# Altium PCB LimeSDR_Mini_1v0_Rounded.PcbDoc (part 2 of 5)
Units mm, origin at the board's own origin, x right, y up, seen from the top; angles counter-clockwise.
Board outline 69.3 x 52.3 mm, 8 copper layers (Top, L2, L3, L4, L5, L6, L7, Bottom), stack 1.555 mm thick; 371 components, 281 nets, 1644 pads, 778 vias.
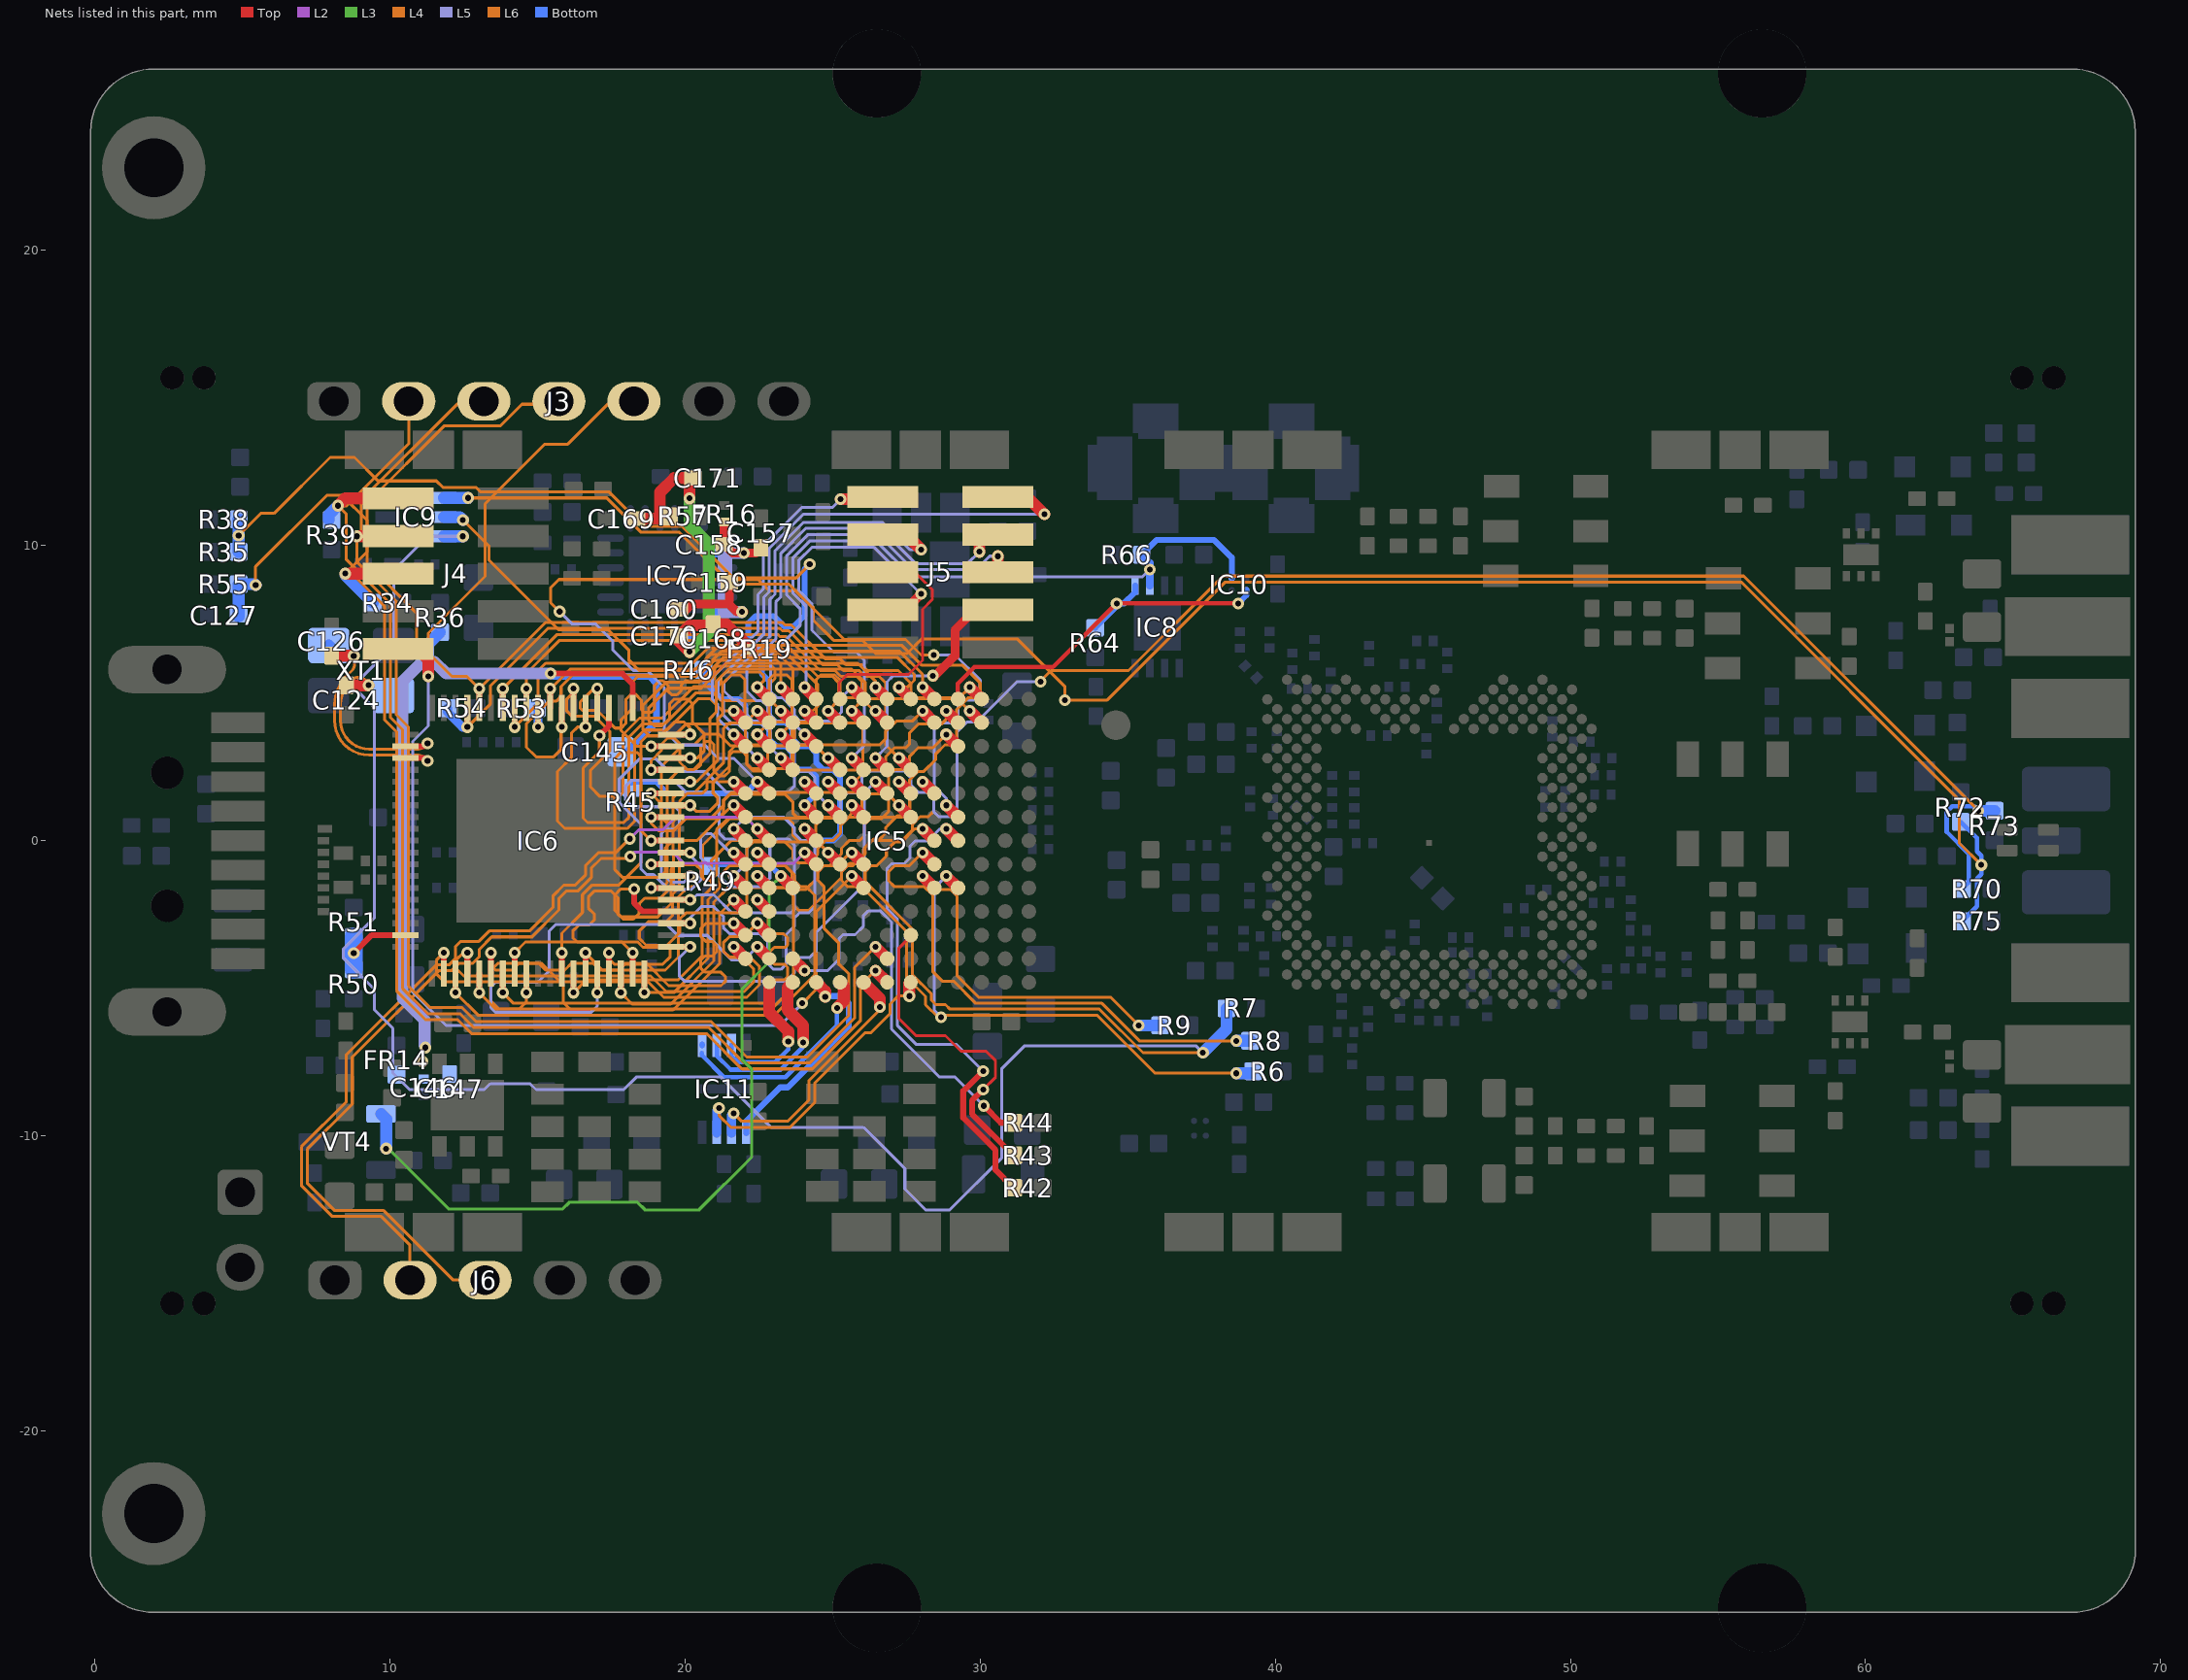
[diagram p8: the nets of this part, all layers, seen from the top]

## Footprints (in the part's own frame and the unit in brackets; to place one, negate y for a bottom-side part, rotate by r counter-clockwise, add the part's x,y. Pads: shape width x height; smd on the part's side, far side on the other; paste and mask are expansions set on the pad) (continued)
RES0805#1 [mm] "Chip Resistor, Body 2.0x1.2mm, 0805, IPC Medium Density"
  round 0.254 on Mech14: 0(0,0)
  rrect25% 0.8x1.3 smd: 1(-1,0) 2(1,0)
  Top pour cut-out: -0.6,0.75 0.6,0.75 0.6,-0.75 -0.6,-0.75
  silkscreen extent -0.38,-0.64 0.38,0.64, body extent -1.1,-0.67 1.1,0.68, height 0.69
RES0805#2 [mm] "Chip Resistor, Body 2.0x1.2mm, 0805, IPC Medium Density"
  round 0.254 on Mech15: 0(0,0)
  rrect25% 0.8x1.3 smd: 1(-1,0) 2(1,0)
  Top pour cut-out: -0.6,0.75 0.6,0.75 0.6,-0.75 -0.6,-0.75
  silkscreen extent -0.38,-0.63 0.38,0.64, body extent -1.1,-0.67 1.1,0.68, height 0.69
RES0805_0603 [mm] "Universal 0805 0603 footprint"
  round 0.254 on Mech15: 0(0,0)
  rrect25% 1x1.3 smd paste-3: 1(-0.9,0) 2(0.9,0)
  Top pour cut-out: -0.4,0.725 0.4,0.725 0.4,-0.775 -0.4,-0.775
  silkscreen extent -0.23,-0.7 0.23,0.7, body extent -1.1,-0.67 1.1,0.68, height 0.69
RFI_SHIELD_CLPS_MINI [mm] "RFI SHIELD CLIP MINI TIN SMD, S0971-46R"
  rect 2x1.3 smd mask+0.05: 1(-2,0) 1(2,0)
  rect 1.4x1.3 smd mask+0.05: 1(0,0)
  body extent -2.9,-0.5 2.9,0.5, height 1
SKY13411-374LF [mm]
  rect 0.35x0.25 smd mask+0.05: 1(-0.725,0.5) 2(-0.725,0) 3(-0.725,-0.5) 4(0.725,-0.5) 5(0.725,0) 6(0.725,0.5)
  rect 0.7x1.2 smd mask+0.05: PAD(0,0)
  silkscreen extent -1.14,-0.8 0.7,0.86, body extent -0.75,-0.75 0.75,0.75, height 0.48
SMA_CONNECTOR_BOARD_EDGE_SM [mm]
  rect 2x4.25 smd: 1(0,0)
  rect 2x4 smd far side: 2(-2.77,-0.1) 2(2.77,-0.1)
  rect 2x4 smd: 2(-2.77,-0.1) 2(2.77,-0.1)
  silkscreen extent -4.3,-1.9 4.3,2.5, body extent -3,-11.8 3,1.8, height 3.4
SOT23-3 [mm] "SOT23, 3 pin"
  round 0.5 on Mech14: 0(0,0)
  rrect25% 1x0.6 smd: D(1.15,0) G(-1.15,0.95) S(-1.15,-0.95)
  silkscreen extent -1.25,-1.45 0.38,1.81, body extent -1.4,-1.45 1.4,1.45, height 1.29
SWD_10_pin [mm]
  rect 0.75x2.4 smd: 1(-2.55,-1.95) 2(-2.55,1.95) 3(-1.275,-1.95) 4(-1.275,1.95) 5(0,-1.95) 6(0,1.95) 7(1.275,-1.95) 8(1.275,1.95) 9(2.55,-1.95) 10(2.55,1.95)
  silkscreen extent -3.2,-3.4 3.2,3.4, body extent -3.17,-2.75 3.17,2.75, height 6.37
USB3A_SM [mm]
  rect 0.7x1.8 smd: 1(-3,-1.2) 2(-1,-1.2) 3(1,-1.2) 4(3,-1.2) 5(4,-1.2) 6(2,-1.2) 7(0,-1.2) 8(-2,-1.2) 9(-4,-1.2)
  oval 1.6x4 hole 1 slot 2.5 at 90 deg: 10(-5.8,1.2) 10(5.8,1.2)
  round 1.1 hole 1.1 unplated: 11(-2.2,1.2) 11(2.3,1.2)
  silkscreen extent -6.95,-2.55 7.05,3.6, body extent -6,-1.75 6,19, height 1.8
W25Q40EWUXIE_8-USON [mm]
  rect 0.8x0.3 smd mask+0.05: 1(-1.475,0.75) 2(-1.475,0.25) 3(-1.475,-0.25) 4(-1.475,-0.75) 5(1.475,-0.75) 6(1.475,-0.25) 7(1.475,0.25) 8(1.475,0.75)
  rect 0.3x1.8 smd mask+0.05: PAD(0,0)
  silkscreen extent -1.55,-1.1 1,1.27, body extent -1.51,-1 1.51,1, height 0.6
WURTHELECTRONIC_RF_SHIELD [mm] "Man. part nr.: 36003250"
  body extent 0,0 26.8,26.8, height 3.1

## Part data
C1 C2 C3 C4 C5 C6 C7 C8 C9 C10 C11 C12 C13 C14 C15 C16 C17 C18 C19 C20 C21 C22 C23 C24 C25 C26 C27 C28 C29 C30 C31 C32 C33 C34 C35 C36 C37 C38 C39 C40 C41 C42 C43 C44 C45 C46 C47 C48 C49 C50 C51 C52 C53 C54 C55 C56 C57 C58 C59 C60 C61 C62 C63 C64 C65 C66 C67 C68 C69 C70 C71 C72 C73 C74 C75 C76 C77 C78 C79 C80 C81 C82 C83 C84 C85 C86 C87 C89 C90 C91 C92 C93 C94 C96 C97 C98 C99 C100 C101 C103 C104 C105 C106 C107 C109 C110 C111 C113 C114 C115 C116 C117 C118 C119 C120 C121 C122 C124 C126 C129 C130 C131 C132 C133 C134 C135 C136 C138 C139 C140 C141 C142 C143 C144 C146 C147 C148 C149 C151 C152 C153 C154 C155 C156 C157 C158 C159 C160 C161 C164 C165 C166 C167 C168 C169 C170 C171 C173 C178 C179 C183 MN3 MN4 MN5 MN6 MN11 MN12 MN13 MN14 MN15 MN16 MN17 MN18 MN19 MN21 MN22: library part Cap_0402
C88 C95 C102 C108 C112 C123 C125 C127 C128 C137 C145 C150 C162 C163 C172 C174 C175 C176 C177 C180 C181 C182 C184: library part Cap_0603
FR1 FR2 FR3 FR4 FR5 FR6 FR7 FR8 FR9 FR10 FR11 FR12 FR13 FR14 FR15 FR16 FR17 FR18 FR19 FR20 FR21 FR22: library part Ferrite
IC1: library part LMS7002Mr3, "Schematic symbol revision 3. Default footprint - 0.31mm pad"
IC9: library part AD5601BKSZ-REEL7, "Single 8-Bit nanoDAC with SPI Interface in LFCSP and SC70, 2.7 to 5.5 V, <100 uA, -40 to +125 degC, KS-6, Pb-Free, Reel"
IC12 IC13: "LXDC55KAAA-205"
J1 J2: library part RF_IF_connector, "CONN SMA JACK STR 50OHM EDGE MNT"
J3: library part Header7P, "Header, 7-pin"
J4 J5: library part "Header 5X2_SWD", "Header, 5-Pin, Dual row"
J6: library part Header5P, "Header, 5-pin"
J8 J9: library part RF_IF_connector, "CONN UMC RCPT STR 50 OHM SMD"
J10: library part Jumper
LED1: library part LED_green_red_SMD
LED2: library part LED_green_red_right_angle, "160-2033-1-ND"
MECH1 MECH2 MECH3 MECH4 MECH6 MECH8 MECH9 MECH10 MECH11 MECH12 MECH13 MECH14: library part RFI_SHIELD_CLIP
MECH5 MECH7 MECH15: library part RFI_SHIELD_1
MN1 MN2 MN7 MN8 MN20 MN23 MN24: library part Inductor_0603
MN9 MN10 R1 R2 R3 R4 R5 R6 R7 R8 R9 R10 R11 R12 R13 R14 R15 R16 R17 R18 R19 R20 R21 R22 R23 R24 R25 R26 R27 R28 R29 R30 R31 R32 R33 R34 R35 R36 R37 R38 R39 R40 R41 R42 R43 R44 R45 R46 R47 R48 R49 R50 R51 R52 R53 R54 R55 R56 R57 R58 R59 R60 R61 R62 R63 R64 R65 R66 R67 R68 R69 R70 R71 R72 R73 R74 R75 R76 R77 R78 R79 R80 R81 R82 R83 R84 R85: library part Res_0402
VT1 VT2 VT3: library part BF1105R,215
XO1: library part Rakon_RTX5032A
XT1: library part CRYSTAL_19M2, "Oscillator Crystal 25 MHz"

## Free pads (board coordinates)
  round 0.8 hole 0.8 unplated mask+0.05: 0(2.625,15.685) 0(2.625,-15.685) 0(3.7,15.685) 0(3.7,-15.685) 0(65.3,-15.685) 0(65.3,15.685) 0(66.375,-15.685) 0(66.375,15.685)
  round 3 hole 3 unplated mask+0.05: 0(26.5,-26) 0(26.5,26) 0(56.5,-26) 0(56.5,26)
  round 3.5 hole 2 mask+0.05: 2(2,-22.8) 2(2,22.8)

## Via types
v1: diameter 0.4, hole 0.2, Top to Bottom, tented both sides, 544 vias
v2: diameter 0.4, hole 0.2, Top to Bottom, tented top, 113 vias
v3: diameter 0.35, hole 0.2, Top to Bottom, tented top, 87 vias
v4: diameter 0.5, hole 0.2, Top to Bottom, 25 vias
v5: diameter 0.5, hole 0.2, Top to Bottom, tented both sides, 8 vias
v6: diameter 0.35, hole 0.2, Top to Bottom, tented both sides, 1 vias

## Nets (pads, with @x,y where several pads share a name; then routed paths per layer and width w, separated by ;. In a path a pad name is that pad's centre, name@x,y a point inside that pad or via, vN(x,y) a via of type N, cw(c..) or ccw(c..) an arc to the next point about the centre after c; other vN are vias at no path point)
+1.8V_DIG_LMK: C157.2 C158.2 C159.2 C160.2 FR16.2 IC7.2 IC7.6 | length 10.5
  Top w0.3: C160.2@19.775,7.765 19.972,7.765 20.222,8.015 21.5,8.015 ; C158.2@21.325,10.04 21.615,9.75 v1(22,9.75) 22.4,9.75 C157.2@22.575,9.925 ; C158.2@21.325,10.04 FR16.2@21.325,10.795 ; C159.2@21.5,8.75 21.5,8.015 ; v1@22,7.75 21.765,7.75 21.5,8.015
  L5 w0.4: 21.35,7.75 v1(21.925,7.75) ; 21.35,9.75 v1(22,9.75)
  L5 w0.5: 21.35,7.75 21.35,9.75
  Bottom w0.3: IC7.6@21,7.75 IC7.6@21.325,7.75 v1(21.925,7.75) ; IC7.2@21,9.75 IC7.2@21.325,9.75 v1(22,9.75)
+3.3V_DIG_LMK: C168.2 C169.2 C170.2 C171.2 FR19.2 IC7.8 IC7.23 R57.2 | length 14.9
  Top w0.4: C169.2@18.35,10.915 19.15,10.915 19.15,11.807 19.633,12.29 C171.2@20.275,12.29 20.15,12.165 v1(20.15,11.6) ; v1(20.15,6.4) 19.8,6.75 C170.2@19.8,6.94 20.15,7.29 20.95,7.29 C168.2@20.95,7.34 21.395,7.34 FR19.2@22.245,6.49
  L3 w0.4: v1(20.15,6.4) 20.8,7.05 20.8,10.065 20.15,10.715 v1(20.15,11.6)
  L4 w0.4: v1(20.15,6.4) v1@20.157,6.4
  Bottom w0.3: v1(20.15,6.4) IC7.8@20.15,7.075 ; IC7.23@20.15,10.6 IC7.23@20.15,10.925 v1(20.15,11.6)
AVDD_FT: C145.2 C146.2 C147.1 FR14.2 IC6.2 | length 28.3
  Top w0.2: v1(15.45,5.665) 17.876,5.665 18.225,5.316 IC6.2@18.225,4.5
  L5 w0.4: v1@11.175,-6.935 11.175,-6.085 10.425,-5.335 10.425,5.397 11.093,6.065 11.507,6.065 11.907,5.665 v1(15.45,5.665)
  Bottom w0.23: v1(15.45,5.665) 15.55,5.565 18.797,5.565 19.04,5.322 19.04,4.03 C145.2@18.025,3.015
  other v1: 11.1,-7.485 11.2,-7.01
BOM_VER0: IC5.K7 R42.2 | length 17.3
  Top w0.2: v1(30.1,-7.81) 29.425,-8.485 29.425,-9.386 30.525,-10.486 30.525,-11.16 R42.2@31.125,-11.76
  Top w0.4: v1(28.85,0.4) IC5.K7@29.25,0
  L5 w0.1: v1(28.85,0.4) 28.635,0.4 28.225,-0.01 27.8,-0.01 27.625,-0.185 27.625,-0.585 27.425,-0.785 27,-0.785 26.85,-0.935 26.85,-2.31 27.2,-2.66 27.2,-6.269 27.828,-6.898 29.188,-6.898 v1(30.1,-7.81)
BOM_VER1: IC5.H3 R43.2 | length 11
  Top w0.1: IC5.H3@27.65,-3.2 27.65,-3.235 27.25,-3.635 27.25,-6.035 27.825,-6.61 28.825,-6.61 29.35,-7.135 30.2,-7.135 30.525,-7.46 30.525,-8.01 v1(30.1,-8.435)
  Top w0.2: v1(30.1,-8.435) 29.725,-8.81 29.725,-9.262 R43.2@31.127,-10.665
BOM_VER2: IC5.C2 R44.2 | length 14.2
  Top w0.2: v1(30.125,-8.985) 30.7,-9.56 R44.2@31.125,-9.56
  Top w0.4: IC5.C2@23.65,-4 v1(24.05,-4.4)
  L5 w0.1: v1(24.05,-4.4) 24.835,-4.4 25.225,-4.01 25.225,-3.31 25.35,-3.185 25.76,-3.185 26.05,-2.895 26.05,-2.535 26.2,-2.385 26.625,-2.385 27,-2.76 27,-6.385 28.625,-8.01 29.15,-8.01 v1(30.125,-8.985)
FAN_CTRL: IC5.C5 R49.2 VT4.G | length 28.8
  Top w0.4: v2(23.25,-1.2) IC5.C5@23.65,-1.6
  L3 w0.1: v1(9.875,-10.435) 9.95,-10.435 12,-12.485 15.85,-12.485 16.08,-12.255 18.39,-12.255 18.645,-12.51 20.475,-12.51 22.262,-10.723 22.262,-7.747 21.925,-7.41 21.925,-5.035 22.85,-4.11 22.85,-1.6 v2(23.25,-1.2)
  Bottom w0.2: R49.2@20.875,-0.86 20.935,-0.8 22.85,-0.8 v2(23.25,-1.2)
  Bottom w0.4: VT4.G@9.7,-9.26 9.875,-9.435 v1(9.875,-10.435)
FPGA_CONFIG_SEL: IC5.D7 R35.2 R38.2 | length 38.6
  Top w0.4: v2(24.05,0.4) IC5.D7@24.45,0
  L4 w0.1: v1(4.875,10.34) 5.625,11.09 6.075,11.09 7.975,12.99 8.8,12.99 9.6,12.19 11.575,12.19 11.8,11.965 12.925,11.965 13.075,11.815 17.433,11.815 18.598,10.65 19.89,10.65 21.64,8.9 23.76,8.9 v1(24.225,9.365)
  Bottom w0.2: v2(24.05,0.4) 24.45,0 25.016,0 25.25,0.234 25.25,2.166 25.016,2.4 24.684,2.4 24.45,2.634 24.45,2.966 24.216,3.2 23.884,3.2 23.65,3.434 23.65,3.766 23.416,4 23.04,4 22.85,4.19 22.85,5.415 22.6,5.665 22.6,6.315 22.15,6.765 22.15,7.369 22.396,7.615 23.009,7.615 23.359,7.265 23.691,7.265 24.05,7.624 24.05,9.19 v1(24.225,9.365)
  Bottom w0.4: R35.2@4.875,9.79 v1(4.875,10.34) R38.2@4.875,10.89
FPGA_EGPIO0: IC5.B7 J6.2 | length 29.4
  Top w0.4: v2(22.45,0.4) IC5.B7@22.85,0
  L2 w0.1: v1(18.125,0.065) 18.425,0.365 19.25,0.365 19.675,0.79 22.06,0.79 v2(22.45,0.4)
  L6 w0.1: J6.2@10.682,-14.89 10.682,-13.708 9.709,-12.735 8.05,-12.735 7,-11.685 7,-10.369 8.525,-8.844 8.525,-7.252 11.567,-4.21 12,-4.21 12.225,-3.985 12.225,-3.585 12.4,-3.41 13.017,-3.41 13.367,-3.06 14.731,-3.06 15.525,-2.266 15.525,-1.877 15.892,-1.51 16.281,-1.51 16.625,-1.166 16.625,-0.851 17.076,-0.4 17.66,-0.4 v1(18.125,0.065)
FPGA_EGPIO1: IC5.D6 J6.3 | length 31.9
  Top w0.4: v2(24.05,-0.4) IC5.D6@24.45,-0.8
  L2 w0.1: v1(18.15,-0.535) 18.3,-0.385 19.575,-0.385 19.95,-0.76 23.69,-0.76 v2(24.05,-0.4)
  L6 w0.1: J6.3@13.225,-14.89 12.147,-14.89 9.792,-12.535 8.133,-12.535 7.2,-11.602 7.2,-10.452 8.725,-8.927 8.725,-7.335 11.65,-4.41 12.083,-4.41 12.333,-4.16 12.8,-4.16 13.025,-3.935 13.025,-3.685 13.45,-3.26 14.814,-3.26 15.725,-2.349 15.725,-1.96 15.975,-1.71 16.364,-1.71 16.825,-1.249 16.825,-0.934 17.159,-0.6 18.085,-0.6 v1(18.15,-0.535)
FPGA_GPIO0: IC5.A11 J5.1 | length 12.7
  Top w0.4: v2(21.65,3.6) IC5.A11@22.05,3.2 ; v1(25.275,11.575) J5.1@26.7,11.575
  L5 w0.1: v2(21.65,3.6) 21.1,4.15 21.1,4.632 20.92,4.812 20.92,5.531 22.475,7.086 22.475,8.339 22.65,8.514 22.65,9.99 23.95,11.29 24.99,11.29 v1(25.275,11.575)
FPGA_GPIO1: IC5.B10 J5.2 | length 20.7
  Top w0.4: v2(22.45,2.8) IC5.B10@22.85,2.4 ; J5.2@30.6,11.65 31.59,11.65 v1(32.175,11.065)
  L5 w0.1: v2(22.45,2.8) 22.1,3.15 22.1,3.645 21.795,3.95 21.605,3.95 21.3,4.255 21.3,4.715 21.12,4.895 21.12,5.448 22.675,7.003 22.675,8.256 22.85,8.431 22.85,9.907 24.008,11.065 v1(32.175,11.065)
FPGA_GPIO2: IC5.C10 J5.3 | length 16.5
  Top w0.4: v2(23.25,2.8) IC5.C10@23.65,2.4 ; J5.3@26.7,10.375 27.49,10.375 v1(28,9.865)
  L5 w0.1: v2(23.25,2.8) 22.9,3.15 22.9,3.645 22.495,4.05 22.305,4.05 22.1,4.255 22.1,4.445 21.773,4.772 21.623,4.772 21.32,5.075 21.32,5.365 22.875,6.92 22.875,8.173 23.05,8.348 23.05,9.824 24.005,10.78 26.701,10.78 27.616,9.865 v1(28,9.865)
FPGA_GPIO3: IC5.D11 J5.4 | length 16.7
  Top w0.4: v2(24.05,3.6) IC5.D11@24.45,3.2 ; v1(29.975,9.79) J5.4@29.975,10.375
  L5 w0.1: v2(24.05,3.6) 23.6,4.05 23.105,4.05 22.8,4.355 22.8,4.545 22.595,4.75 22.405,4.75 22.1,5.055 22.1,5.862 23.075,6.837 23.075,8.09 23.25,8.265 23.25,9.741 24.088,10.58 26.618,10.58 27.808,9.39 29.575,9.39 v1(29.975,9.79)
FPGA_GPIO4: IC5.E13 J5.5 | length 8.2
  Top w0.1: IC5.E13@25.25,4.8 25.217,4.833 25.217,5.357 25.493,5.633 27.57,5.633 28.05,6.113 28.05,7.84 28.375,8.165 28.375,8.515 27.79,9.1 J5.5@26.7,9.1
FPGA_GPIO5: IC5.F13 J5.6 | length 18.5
  Top w0.4: v2(25.65,5.2) IC5.F13@26.05,4.8 ; J5.6@30.6,9.1 v1(30.6,9.64)
  L5 w0.1: v2(25.65,5.2) 25.3,4.85 25.3,4.355 24.995,4.05 23.905,4.05 23.7,4.255 23.7,4.445 23.295,4.85 23.105,4.85 22.9,5.055 22.9,6.29 23.9,7.29 23.9,7.865 23.45,8.315 23.45,9.659 24.156,10.365 26.55,10.365 27.725,9.19 29.87,9.19 30.32,9.64 v1(30.6,9.64)
FPGA_GPIO6: IC5.F10 J5.7 | length 15.3
  Top w0.3: J5.7@26.7,7.825 27.46,7.825 v1(28,8.365)
  Top w0.4: v2(25.65,2.8) IC5.F10@26.05,2.4
  L5 w0.1: v2(25.65,2.8) 26.075,3.225 26.075,6.115 25.8,6.39 25.042,6.39 24.3,7.132 24.3,8.031 23.85,8.481 23.85,9.493 24.297,9.94 26.409,9.94 27.984,8.365 v1(28,8.365)
FPGA_GPIO7: IC5.G10 J5.8 | length 8.6
  Top w0.3: v1@28.425,5.54 29.15,6.265 29.15,7.14 29.835,7.825 J5.8@30.6,7.825
  Top w0.4: v2(26.45,2.8) IC5.G10@26.85,2.4
  L5 w0.1: v2(26.45,2.8) 26.85,3.2 26.85,5.39 27.05,5.59 v1(28.4,5.59)
FPGA_I2C_SCL: IC5.D13 IC8.2 IC10.A2 R66.2 | length 23.5
  Top w0.4: v2(24.05,5.2) IC5.D13@24.45,4.8
  L5 w0.1: v2(24.05,5.2) 24.1,5.25 24.1,7.948 23.65,8.398 23.65,9.576 24.239,10.165 26.467,10.165 27.692,8.94 35.5,8.94 v1(35.75,9.19)
  Bottom w0.2: R66.2@35.475,9.69 35.975,10.19 37.925,10.19 38.525,9.59 IC10.A2@38.525,8.89
  Bottom w0.25: R66.2@35.475,9.69 35.75,9.415 v1(35.75,9.19) IC8.2@35.75,8.64
FPGA_I2C_SDA: IC5.K13 IC8.1 IC10.B1 R64.2 | length 13.9
  Top w0.15: IC5.K13@29.192,4.858 IC5.K13@29.25,4.8 29.25,5.33 29.81,5.89 32.475,5.89 v1(34.625,8.04) v1(38.75,8.04)
  Bottom w0.2: R64.2@33.9,7.215 34.625,7.94 v1(34.625,8.04) 34.875,8.04 35.25,8.415 IC8.1@35.25,8.64 ; v1(38.75,8.04) 39.025,8.315 IC10.B1@39.025,8.49
FPGA_JTAG_TCK: IC5.G2 J3.2 J4.1 R39.1 | length 44.9
  Top w0.4: v1(8.235,11.35) 8.485,11.6 J4.1@10.275,11.6 ; v2(26.45,-3.6) IC5.G2@26.85,-4
  L4 w0.1: v1(8.235,11.35) 8.525,11.06 8.525,9.524 9.567,8.482 10.012,8.035 10.012,4.185 10.425,3.773 10.425,-5.002 11.283,-5.86 12.369,-5.86 12.844,-6.335 20.808,-6.335 22.008,-7.535 24.225,-7.535 25.75,-6.01 25.75,-4.3 v2(26.45,-3.6)
  L6 w0.1: v1(8.235,11.35) 8.535,11.35 10.639,13.454 J3.2@10.639,14.79
  Bottom w0.4: R39.1@7.925,10.865 7.925,11.04 v1(8.235,11.35)
FPGA_JTAG_TDI: IC5.F5 J3.5 J4.9 R36.1 | length 47
  Top w0.4: J4.9@10.275,6.5 10.94,6.5 11.3,6.14 v1(11.3,5.565) ; v2(25.65,-1.2) IC5.F5@26.05,-1.6
  L5 w0.1: v1(11.3,5.565) 11.3,3.89 10.775,3.365 10.775,-5.135 11.9,-6.26 23.225,-6.26 v1(23.975,-5.51)
  L6 w0.1: v1(11.3,5.565) 11.3,7.035 13.225,8.96 13.225,11.415 15.25,13.44 16.03,13.44 17.38,14.79 J3.5@18.268,14.79 ; v1(23.975,-5.51) 24.45,-5.035 24.45,-2.4 v2(25.65,-1.2)
  Bottom w0.4: v1(11.3,5.565) 11.3,6.665 R36.1@11.7,7.065
FPGA_JTAG_TDO: IC5.F6 J3.3 J4.3 | length 48
  Top w0.4: v1(8.875,10.315) 10.265,10.315 J4.3@10.275,10.325 ; v2(25.65,-0.4) IC5.F6@26.05,-0.8
  L4 w0.1: v1(8.875,10.315) 8.875,9.457 9.771,8.561 9.771,8.56 10.212,8.118 10.212,4.268 10.625,3.856 10.625,-4.919 11.366,-5.66 12.452,-5.66 12.927,-6.135 20.891,-6.135 22.091,-7.335 24.142,-7.335 25.55,-5.927 25.55,-4.51 25.2,-4.16 25.2,-3.455 24.705,-2.96 24.705,-1.55 24.5,-1.345 24.5,-1.055 24.705,-0.85 25.16,-0.85 25.61,-0.4 v2(25.65,-0.4)
  L6 w0.1: v1(8.875,10.315) 9.025,10.465 9.025,11.54 12.275,14.79 J3.3@13.182,14.79
FPGA_JTAG_TMS: IC5.G1 J3.4 J4.5 R34.1 | length 48.7
  Top w0.4: v1(8.485,9.05) J4.5@10.275,9.05 ; v2(26.45,-4.4) IC5.G1@26.85,-4.8
  L4 w0.1: v1(8.485,9.05) 8.715,9.05 9.812,7.953 9.812,4.103 10.225,3.69 10.225,-5.085 11.2,-6.06 12.286,-6.06 12.761,-6.535 20.725,-6.535 21.925,-7.735 24.308,-7.735 25.95,-6.093 25.95,-4.9 v2(26.45,-4.4)
  L6 w0.1: v1(8.485,9.05) 9.225,9.79 9.225,11.44 11.85,14.065 13.75,14.065 14.475,14.79 J3.4@15.725,14.79
  Bottom w0.4: v1(8.485,9.05) 8.485,9.005 R34.1@9.425,8.065
FPGA_LED_G: IC5.D8 R46.2 R70.2 R73.2 | length 63.1
  Top w0.4: v2(24.05,1.2) IC5.D8@24.45,0.8
  L4 w0.1: v1@31.975,5.34 32.4,5.765 35.025,5.765 38.225,8.965 55.875,8.965 v1(63.825,1.015)
  L5 w0.1: v2(24.05,1.2) 24.485,0.765 25.05,0.765 25.275,0.99 25.275,1.39 25.5,1.615 25.782,1.615 26,1.833 26,2.215 26.15,2.365 27.425,2.365 27.65,2.14 27.65,1.89 27.9,1.64 28.2,1.64 28.425,1.415 28.425,0.99 28.6,0.815 29.05,0.815 29.225,0.99 29.225,3.69 29.55,4.015 29.875,4.015 31.25,5.39 v1(32.05,5.39)
  Bottom w0.15: R70.2@63.275,-1.635 63.5,-1.41 63.5,-0.447 62.75,0.303 62.75,0.977 62.938,1.165 63.675,1.165 v1(63.825,1.015)
  Bottom w0.2: R46.2@20.675,5.79 20.675,5.38 21.255,4.8 21.816,4.8 22.05,4.566 22.05,4.234 22.284,4 22.616,4 22.85,3.766 22.85,3.434 23.084,3.2 23.416,3.2 23.65,2.966 23.65,2.59 23.84,2.4 24.216,2.4 24.45,2.166 24.45,1.6 v2(24.05,1.2)
  Bottom w0.4: v1(63.825,1.015) R73.2@64.375,1.015
FPGA_LED_R: IC5.B9 R45.2 R72.2 R75.2 | length 77.9
  Top w0.4: v2(22.45,2) IC5.B9@22.85,1.6
  L4 w0.1: v1(32.875,4.765) 34.308,4.765 38.308,8.765 55.792,8.765 63.175,1.382 63.175,-0.073 v1(63.925,-0.823)
  L5 w0.1: v1(15.75,7.765) 16.175,7.34 16.975,7.34 17.55,6.765 17.55,6.465 18.25,5.765 18.725,5.765 19.3,5.19 19.3,3.74 19.8,3.24 20.675,3.24 21.125,2.79 21.66,2.79 v2(22.45,2)
  L6 w0.1: v1(15.75,7.765) 15.45,8.065 15.45,8.575 15.725,8.85 22.481,8.85 22.874,8.457 23.808,8.457 24.35,7.915 24.35,7.473 25.033,6.79 26.008,6.79 26.458,6.34 27.525,6.34 28.025,6.84 31.25,6.84 32.875,5.215 v1(32.875,4.765)
  Bottom w0.15: R72.2@63.225,0.64 63.775,0.09 63.775,-0.36 63.925,-0.51 v1(63.925,-0.823) 63.925,-1.135 63.775,-1.285 63.775,-2.224 R75.2@63.264,-2.735
  Bottom w0.19: R45.2@18.175,1.965 18.205,1.995 19.014,1.995 19.409,1.6 22.05,1.6
  Bottom w0.2: 22.05,1.6 v2(22.45,2)
FPGA_QSPI_FLASH_SS: IC5.E1 IC11.1 | length 7.3
  Top w0.1: IC5.E1@25.25,-4.8 IC5.E1@25.375,-4.925
  Top w0.4: v1(25.15,-5.666) 25.375,-5.441 IC5.E1@25.375,-4.925
  Bottom w0.15: IC11.1@20.575,-7.193 20.575,-7.268 21.317,-8.01 23.408,-8.01 25.15,-6.268 v1(25.15,-5.666)
  Bottom w0.2: IC11.1@20.575,-6.935 IC11.1@20.575,-6.91
FPGA_QSPI_IO0: IC5.D1 IC11.5 | length 7.5
  Top w0.4: IC5.D1@24.45,-4.8 24.75,-5.1 v1(24.75,-5.285)
  Bottom w0.2: IC11.5@22.075,-9.91 22.075,-9.51 23.225,-8.36 23.482,-8.36 25.55,-6.292 25.55,-5.5 25.316,-5.266 24.769,-5.266 v1(24.75,-5.285)
FPGA_QSPI_IO1: IC5.C1 IC11.2 | length 6.2
  Top w0.4: IC5.C1@23.65,-4.8 23.475,-4.975 23.475,-5.735 24,-6.26 v1@24,-6.785
  Bottom w0.15: IC11.2@21.075,-6.91 21.075,-7.285 21.55,-7.76 23.233,-7.76 24,-6.993 v1(24,-6.835)
FPGA_QSPI_IO2: IC5.B1 IC11.3 | length 5.1
  Top w0.4: IC5.B1@22.85,-4.8 22.85,-5.817 23.5,-6.467 v1(23.5,-6.81)
  Bottom w0.15: IC11.3@21.575,-6.91 21.575,-7.285 21.8,-7.51 23.059,-7.51 23.5,-7.069 v1(23.5,-6.81)
FPGA_QSPI_IO3: IC5.H1 IC11.7 | length 10.6
  Top w0.4: v2@27.6,-5.235 27.6,-4.85 IC5.H1@27.65,-4.8
  L4 w0.1: v1(21.15,-9.06) 21.15,-9.31 21.55,-9.71 23.558,-9.71 24.4,-8.868 24.4,-8.209 26.099,-6.51 26.3,-6.51 26.95,-5.86 26.95,-5.535 27.219,-5.266 v2(27.6,-5.266)
  Bottom w0.3: IC11.7@21.075,-9.91 21.075,-9.135 v1(21.15,-9.06)
FPGA_QSPI_SCLK: IC5.F1 IC11.6 | length 8.9
  Top w0.4: IC5.F1@26.05,-4.8 26.6,-5.35 v1(26.6,-5.635)
  L4 w0.1: v1(21.65,-9.235) 21.925,-9.51 23.475,-9.51 24.2,-8.785 24.2,-8.126 26.6,-5.726 v1(26.6,-5.635)
  Bottom w0.3: IC11.6@21.575,-9.91 21.575,-9.31 v1(21.65,-9.235)
FPGA_SPI_DAC_SS: IC5.K8 IC9.1 | length 26.8
  Top w0.4: v2(28.85,1.2) IC5.K8@29.25,0.8
  L4 w0.1: v1(12.65,11.615) 17.35,11.615 18.515,10.45 19.807,10.45 21.557,8.7 23.51,8.7 25.395,6.815 27.475,6.815 28,6.29 v1(28.425,6.29)
  L5 w0.1: v1(28.425,6.29) 29.15,6.29 30,5.44 30,5.055 30,4.99 29.775,4.765 29.425,4.765 29.25,4.59 29.25,4.19 29.05,3.99 28.65,3.99 28.45,3.79 28.45,1.84 28.85,1.44 v2(28.85,1.2)
  Bottom w0.4: IC9.1@11.825,11.615 v1(12.65,11.615)
FPGA_SPI_LMS_SS: IC5.J5 R9.2 | length 12.3
  Top w0.4: v2(28.05,-1.2) IC5.J5@28.45,-1.6
  L4 w0.1: v2(28.05,-1.2) 28.5,-1.65 28.995,-1.65 29.225,-1.88 29.225,-4.585 29.95,-5.31 34.428,-5.31 v1(35.375,-6.257)
  Bottom w0.4: v1(35.375,-6.257) R9.2@36.1,-6.257
FPGA_SPI_MISO: IC5.J6 R8.2 | length 18.3
  Top w0.4: v2(28.05,-0.4) IC5.J6@28.45,-0.8
  L4 w0.1: v2(28.05,-0.4) 27.6,-0.85 27.105,-0.85 26.9,-1.055 26.9,-1.36 27.09,-1.55 28.095,-1.55 28.4,-1.855 28.4,-4.445 28.715,-4.76 29.1,-4.76 29.85,-5.51 34.125,-5.51 35.397,-6.782 v1(38.675,-6.782)
  Bottom w0.4: v1(38.675,-6.782) R8.2@39.15,-6.782
FPGA_SPI_MOSI: IC5.J7 IC9.3 R7.2 | length 77.1
  Top w0.4: v2(28.05,0.4) IC5.J7@28.45,0
  L4 w0.1: v2(28.05,0.4) 27.785,0.4 27.335,-0.05 27.105,-0.05 26.825,-0.33 26.825,-0.52 26.495,-0.85 26.305,-0.85 26.1,-1.055 26.1,-1.385 27.7,-2.985 27.7,-4.545 28.35,-5.195 28.35,-5.41 28.498,-5.558 28.825,-5.558 28.977,-5.71 34.042,-5.71 35.517,-7.185 v1(37.55,-7.185)
  L5 w0.1: v1(12.475,10.315) 11.284,10.315 10.125,9.156 10.125,6.61 8.925,5.41 8.925,5.048 9.475,4.498 9.475,-2.619 9.471,-2.619 8.425,-3.665 8.425,-3.985 9.475,-5.035 9.475,-5.729 10.1,-6.354 10.1,-7.871 10.664,-8.435 13.2,-8.435 13.4,-8.235 14.75,-8.235 14.95,-8.435 17.925,-8.435 18.35,-8.01 21.21,-8.01 22.91,-9.71 26.05,-9.71 27.45,-11.11 27.45,-11.81 28.15,-12.51 28.975,-12.51 30.725,-10.76 30.725,-7.73 31.495,-6.96 37.325,-6.96 v1(37.55,-7.185)
  Bottom w0.4: IC9.3@11.825,10.315 v1(12.475,10.315) ; v1(37.55,-7.185) 38.35,-6.385 R7.2@38.35,-5.682
FPGA_SPI_SCLK: IC5.K5 IC9.2 R6.2 | length 54.2
  Top w0.4: v2(28.85,-1.2) IC5.K5@29.25,-1.6
  L4 w0.1: v1(12.475,10.865) 13.362,9.977 13.362,9.503 15.725,7.14 17.408,7.14 18.1,6.448 18.1,6.115 18.45,5.765 20.3,5.765 21.15,6.615 27.355,6.615 28.03,5.94 29.405,5.94 30,5.345 30,5.055 29.795,4.85 29.605,4.85 29.2,4.445 29.2,3.455 28.995,3.25 28.805,3.25 28.5,2.945 28.5,2.755 28.095,2.35 27.905,2.35 27.6,2.045 27.6,1.055 27.395,0.85 27.205,0.85 26.8,0.445 26.8,0.255 26.595,0.05 26.385,0.05 26.1,-0.235 26.1,-0.445 25.695,-0.85 25.505,-0.85 25.3,-1.055 25.3,-1.345 25.515,-1.56 25.992,-1.56 27.5,-3.068 27.5,-4.628 28.15,-5.278 28.15,-5.56 28.575,-5.985 v1(28.675,-5.985) ; v1@28.782,-5.91 33.959,-5.91 35.932,-7.882 v1(38.675,-7.882)
  L5 w0.1: v1(28.675,-5.985) 28.45,-5.76 28.45,-1.6 v2(28.85,-1.2)
  Bottom w0.4: IC9.2@11.825,10.965 12.375,10.965 v1(12.475,10.865) ; v1(38.675,-7.882) R6.2@39.15,-7.882
FT_BE0: IC5.B11 IC6.4 | length 15.7
  Top w0.2: v1(17.1,3.565) 17.425,3.89 IC6.4@17.425,4.5
  Top w0.4: v2(22.45,3.6) IC5.B11@22.85,3.2
  L6 w0.1: v1(17.1,3.565) 17.1,3.015 16.55,2.465 16.55,0.765 16.7,0.615 17.925,0.615 18.1,0.79 18.1,3.511 18.539,3.95 19.307,3.95 20.372,5.015 20.95,5.015 21.215,4.75 22.595,4.75 22.8,4.545 22.8,3.95 v2(22.45,3.6)
FT_BE1: IC5.C12 IC6.5 | length 14.1
  Top w0.2: IC6.5@17.025,4.5 v1(17.025,5.15)
  Top w0.4: v2(23.25,4.4) IC5.C12@23.65,4
  L6 w0.1: v1(17.025,5.15) 16.9,5.15 16.45,4.7 16.45,4.49 16.525,4.415 17.028,4.415 17.628,3.815 17.839,3.815 18,3.976 18,4.79 18.175,4.965 18.315,4.965 18.525,4.755 18.525,4.44 18.615,4.35 18.86,4.35 18.975,4.465 18.975,5.265 19.125,5.415 19.275,5.415 19.425,5.265 19.425,5.065 19.55,4.94 19.732,4.94 19.875,5.083 19.875,5.277 20.013,5.415 20.9,5.415 21,5.515 21,5.832 21.083,5.915 22.95,5.915 23.05,5.815 23.05,5.495 22.875,5.32 22.875,4.775 v2(23.25,4.4)
FT_BE2: IC5.A12 IC6.6 | length 14.6
  Top w0.2: v1(16.625,3.85) IC6.6@16.625,4.5
  Top w0.4: v2(21.65,4.4) IC5.A12@22.05,4
  L6 w0.1: v1(16.625,3.85) 16.36,3.85 16.15,3.64 16.15,2.815 15.675,2.34 15.675,0.665 15.925,0.415 18.05,0.415 18.3,0.665 18.3,3.428 18.622,3.75 19.39,3.75 20.455,4.815 20.85,4.815 21.265,4.4 v2(21.65,4.4)
FT_BE3: IC5.B13 IC6.7 | length 15.6
  Top w0.2: IC6.7@16.225,4.5 v1(16.225,5.15)
  Top w0.4: v2(22.45,5.2) IC5.B13@22.85,4.8
  L6 w0.1: v1(16.225,5.15) 16.21,5.15 16.21,5.017 15.983,4.79 15.983,4.407 16.175,4.215 16.945,4.215 17.45,3.71 17.45,3.04 16.8,2.39 16.8,1.815 17.115,1.5 17.76,1.5 17.9,1.64 17.9,3.593 18.457,4.15 19.224,4.15 20.289,5.215 21.1,5.215 21.225,5.34 21.225,5.565 21.375,5.715 22.55,5.715 22.675,5.59 22.675,5.425 v2(22.45,5.2)
FT_CLK: IC5.G9 IC6.58 | length 14.2
  Top w0.2: IC6.58@19.525,-3.6 v1(20.175,-3.6)
  Top w0.4: v2(26.45,2) IC5.G9@26.85,1.6
  L5 w0.1: v1(20.175,-3.6) 19.8,-3.975 19.8,-4.585 19.975,-4.76 23.425,-4.76 23.7,-4.485 23.7,-4.185 23.925,-3.96 24.225,-3.96 24.45,-3.735 24.45,-3.11 26.075,-1.485 26.075,1.625 v2(26.45,2)
FT_D0: IC5.A2 IC6.40 | length 15.3
  Top w0.2: IC6.40@11.825,-4.5 v1@11.825,-3.85
  Top w0.4: v2(21.65,-3.6) IC5.A2@22.05,-4
  L4 w0.1: v1(11.825,-3.8) 11.575,-4.05 11.575,-4.51 11.85,-4.785 18.755,-4.785 19.28,-5.31 22.092,-5.31 22.525,-4.877 22.525,-4.26 21.865,-3.6 v2(21.65,-3.6)
FT_D1: IC5.B6 IC6.41 | length 19.6
  Top w0.2: v1(12.225,-5.15) IC6.41@12.225,-4.5
  Top w0.4: v2(22.45,-0.4) IC5.B6@22.85,-0.8
  L4 w0.1: v1(12.225,-5.15) 12.985,-5.91 23.035,-5.91 24.4,-4.545 24.4,-1.855 24.095,-1.55 23.905,-1.55 23.7,-1.345 23.7,-1.155 23.355,-0.81 22.86,-0.81 v2(22.45,-0.4)
FT_D2: IC5.B3 IC6.42 | length 16
  Top w0.2: IC6.42@12.625,-4.5 v1@12.625,-3.85
  Top w0.4: v2(22.45,-2.8) IC5.B3@22.85,-3.2
  L4 w0.1: v1(12.625,-3.8) 12.485,-3.8 12.25,-4.035 12.25,-4.335 12.5,-4.585 18.838,-4.585 19.363,-5.11 22.009,-5.11 22.325,-4.794 22.325,-4.343 21.932,-3.95 21.505,-3.95 21.3,-3.745 21.3,-3.455 21.505,-3.25 22,-3.25 v2(22.45,-2.8)
FT_D3: IC5.B5 IC6.43 | length 17
  Top w0.2: v1(13.025,-5.15) IC6.43@13.025,-4.5
  Top w0.4: v2(22.45,-1.2) IC5.B5@22.85,-1.6
  L4 w0.1: v1(13.025,-5.15) 13.585,-5.71 22.925,-5.71 23.675,-4.96 23.675,-1.885 23.375,-1.585 22.835,-1.585 v2(22.45,-1.2)
FT_D4: IC5.A3 IC6.44 | length 14.9
  Top w0.2: IC6.44@13.425,-4.5 v1@13.425,-3.85
  Top w0.4: v2(21.65,-2.8) IC5.A3@22.05,-3.2
  L4 w0.1: v1(13.425,-3.8) 13.425,-4.235 13.575,-4.385 14.135,-4.385 14.36,-4.16 15.05,-4.16 15.275,-4.385 15.925,-4.385 16.16,-4.15 16.89,-4.15 17.125,-4.385 17.75,-4.385 17.985,-4.15 18.686,-4.15 19.446,-4.91 21.225,-4.91 21.375,-4.76 21.375,-4.62 21.215,-4.46 20.675,-4.46 20.525,-4.31 20.525,-4.06 20.675,-3.91 20.925,-3.91 21.075,-3.76 21.075,-3.56 20.925,-3.41 20.7,-3.41 20.525,-3.235 20.525,-2.985 20.71,-2.8 v2(21.65,-2.8)
FT_D5: IC5.B4 IC6.45 | length 15.9
  Top w0.2: v1(13.825,-5.15) IC6.45@13.825,-4.5
  Top w0.4: v2(22.45,-2) IC5.B4@22.85,-2.4
  L4 w0.1: v1(13.825,-5.15) 14.185,-5.51 22.675,-5.51 22.85,-5.335 22.85,-4.835 22.975,-4.71 23.375,-4.71 23.475,-4.61 23.475,-4.285 23.375,-4.185 23.025,-4.185 22.825,-3.985 22.825,-3.81 23.025,-3.61 23.4,-3.61 23.475,-3.535 23.475,-3.285 23.34,-3.15 22.99,-3.15 22.825,-2.985 22.825,-2.375 v2(22.45,-2)
FT_D6: IC5.E6 IC6.46 | length 15.1
  Top w0.2: IC6.46@14.225,-4.5 v1@14.225,-3.85
  Top w0.4: v2(24.85,-0.4) IC5.E6@25.25,-0.8
  L4 w0.1: v1(14.225,-3.8) 14.59,-3.435 18.4,-3.435 18.575,-3.61 19.325,-3.61 19.825,-3.11 19.825,-2.655 20.03,-2.45 21.86,-2.45 22.1,-2.21 22.1,-0.255 22.305,-0.05 24.5,-0.05 v2(24.85,-0.4)
FT_D7: IC5.A4 IC6.47 | length 15.9
  Top w0.2: v1(14.625,-5.15) IC6.47@14.625,-4.5
  Top w0.4: v2(21.65,-2) IC5.A4@22.05,-2.4
  L6 w0.1: v1(14.625,-5.15) 14.625,-5.46 14.375,-5.71 13.7,-5.71 13.4,-5.41 13.4,-4.41 13.65,-4.16 15.15,-4.16 15.875,-4.885 15.875,-5.485 16.125,-5.735 19.6,-5.735 21.175,-4.16 21.175,-2.475 v2(21.65,-2)
FT_D8: IC5.B12 IC6.50 | length 14.4
  Top w0.2: IC6.50@15.825,-4.5 v1@15.825,-3.85
  Top w0.4: v2(22.45,4.4) IC5.B12@22.85,4
  L6 w0.1: v1(15.825,-3.8) 15.825,-3.135 16.525,-2.435 16.525,-1.831 16.856,-1.5 17.76,-1.5 18.5,-0.76 18.5,3.345 18.705,3.55 19.63,3.55 20.03,3.95 22,3.95 v2(22.45,4.4)
FT_D9: IC5.H8 IC6.51 | length 18.2
  Top w0.2: v1(16.225,-5.15) IC6.51@16.225,-4.5
  Top w0.4: v2(27.25,1.2) IC5.H8@27.65,0.8
  L6 w0.1: v1(16.225,-5.15) 16.665,-4.71 19.776,-4.71 20.575,-3.911 20.575,-1.919 20.9,-1.594 20.9,-0.655 21.555,0 23.345,0 23.65,-0.305 23.65,-0.575 23.825,-0.75 24.195,-0.75 24.5,-0.445 24.5,-0.255 24.755,0 25.01,0 25.275,0.265 25.275,0.52 25.545,0.79 25.825,0.79 26.025,0.99 26.025,1.415 26.2,1.59 26.86,1.59 v2(27.25,1.2)
FT_D10: IC5.E9 IC6.52 | length 16.2
  Top w0.2: IC6.52@16.625,-4.5 v1@16.625,-3.85
  Top w0.4: v2(24.85,2) IC5.E9@25.25,1.6
  L6 w0.1: v1(16.625,-3.8) 17.21,-4.385 19.333,-4.385 19.775,-3.943 19.775,-1.905 20.13,-1.55 20.32,-1.55 20.6,-1.27 20.6,-0.155 21.505,0.75 23.49,0.75 23.65,0.59 23.65,0.19 23.84,0 24.26,0 24.425,0.165 24.425,0.525 24.69,0.79 25.05,0.79 25.275,1.015 25.275,1.365 24.85,1.79
FT_D11: IC5.B2 IC6.53 | length 17.5
  Top w0.2: v1(17.025,-5.15) IC6.53@17.025,-4.5
  Top w0.4: v2(22.45,-3.6) IC5.B2@22.85,-4
  L5 w0.1: v1(17.025,-5.15) 17.025,-5.61 16.825,-5.81 13.575,-5.81 13.425,-5.66 13.425,-4.96 13.585,-4.8 15.01,-4.8 15.4,-4.41 15.4,-3.06 15.625,-2.835 19.375,-2.835 19.75,-3.21 20.75,-3.21 21.575,-4.035 22.015,-4.035 v2(22.45,-3.6)
FT_D12: IC5.D9 IC6.54 | length 16.9
  Top w0.2: IC6.54@17.425,-4.5 v1@17.425,-3.85
  Top w0.4: v2(24.05,2) IC5.D9@24.45,1.6
  L6 w0.1: v1(17.425,-3.8) 17.425,-4.01 17.6,-4.185 19.25,-4.185 19.5,-3.935 19.5,-3.685 19.365,-3.55 18.69,-3.55 18.45,-3.31 18.45,-3.06 18.76,-2.75 19.36,-2.75 19.575,-2.535 19.575,-1.818 19.803,-1.59 19.803,0.523 20.03,0.75 21.11,0.75 21.3,0.94 21.3,1.365 21.5,1.565 23.4,1.565 23.65,1.315 23.65,0.94 23.8,0.79 24.225,0.79 24.4,0.965 24.4,1.65 v2(24.05,2)
FT_D13: IC5.J9 IC6.55 | length 18.2
  Top w0.2: v1(17.825,-5.15) IC6.55@17.825,-4.5
  Top w0.4: v2(28.05,2) IC5.J9@28.45,1.6
  L6 w0.1: v1(17.825,-5.15) 18.21,-5.535 19.517,-5.535 20.975,-4.077 20.975,-2.085 21.475,-1.585 23.4,-1.585 23.675,-1.86 23.675,-2.185 23.85,-2.36 24.185,-2.36 25.3,-1.245 25.3,-1.055 25.595,-0.76 25.875,-0.76 26.05,-0.585 26.05,-0.285 26.335,0 27.345,0 27.7,0.355 27.7,0.545 27.97,0.815 28.25,0.815 28.425,0.99 28.425,1.625 v2(28.05,2)
FT_D14: IC5.A9 IC6.56 | length 15
  Top w0.2: IC6.56@18.225,-4.5 v1@18.225,-3.85
  Top w0.4: v2(21.65,2) IC5.A9@22.05,1.6
  L6 w0.1: v1(18.225,-3.8) 17.86,-3.435 16.35,-3.435 16.2,-3.285 16.2,-3.06 16.4,-2.86 16.75,-2.86 16.925,-2.685 16.925,-2.485 16.725,-2.285 16.725,-1.914 16.939,-1.7 17.49,-1.7 17.725,-1.935 17.725,-2.485 17.9,-2.66 18.25,-2.66 18.45,-2.46 18.45,-2.135 18.635,-1.95 19.16,-1.95 19.603,-1.507 19.603,-0.467 19.6,-0.464 19.6,1.465 19.75,1.615 20.3,1.615 20.685,2 v2(21.65,2)
FT_D15: IC5.H9 IC6.57 | length 16.6
  Top w0.2: v1(18.625,-5.15) IC6.57@18.625,-4.5
  Top w0.4: v2(27.25,2) IC5.H9@27.65,1.6
  L6 w0.1: v1(18.625,-5.15) 19.619,-5.15 20.775,-3.994 20.775,-2.002 21.175,-1.602 21.175,-1.18 21.505,-0.85 23.395,-0.85 23.625,-1.08 23.625,-1.45 23.825,-1.65 24.095,-1.65 24.5,-1.245 24.5,-1.055 24.705,-0.85 24.895,-0.85 25.3,-0.445 25.3,-0.255 25.555,0 25.91,0 26.075,0.165 26.075,0.54 26.325,0.79 27.335,0.79 27.625,1.08 27.625,1.625 v2(27.25,2)
FT_D16: IC5.A7 IC6.60 | length 14.4
  Top w0.2: IC6.60@19.525,-2.8 v1(20.175,-2.8)
  Top w0.4: v2(21.65,0.4) IC5.A7@22.05,0
  L5 w0.1: v1(20.175,-2.8) 20.175,-2.61 20.55,-2.235 20.975,-2.235 21.3,-2.56 21.3,-2.945 21.505,-3.15 22.525,-3.15 22.8,-3.425 22.8,-4.16 23,-4.36 23.25,-4.36 23.425,-4.185 23.425,-3.185 23.7,-2.91 23.7,-2.618 23.868,-2.45 24.185,-2.45 24.4,-2.235 24.4,-0.235 24.165,0 23.955,0 23.7,0.255 23.7,0.445 23.355,0.79 22.04,0.79 v2(21.65,0.4)
FT_D17: IC5.F8 IC6.61 | length 15.7
  Top w0.2: v1(18.275,-1.635) 18.275,-2.11 18.565,-2.4 18.875,-2.4 IC6.61@19.525,-2.4
  Top w0.4: v2(25.65,1.2) IC5.F8@26.05,0.8
  L4 w0.1: v1(18.275,-1.635) 17.825,-1.635 17.625,-1.835 17.625,-2.36 17.85,-2.585 19.075,-2.585 19.525,-2.135 19.525,-0.96 19.675,-0.81 20.363,-0.81 20.55,-0.997 20.55,-1.21 20.675,-1.335 20.875,-1.335 21.075,-1.135 21.075,0.39 21.45,0.765 25.5,0.765 25.65,0.915 v2(25.65,1.2)
FT_D18: IC5.A6 IC6.62 | length 14.4
  Top w0.2: IC6.62@19.525,-2 v1(20.175,-2)
  Top w0.4: v2(21.65,-0.4) IC5.A6@22.05,-0.8
  L5 w0.1: v1(20.175,-2) 20.235,-2 20.4,-1.835 20.975,-1.835 21.59,-2.45 23.585,-2.45 23.7,-2.335 23.7,-0.135 23.515,0.05 23.11,0.05 22.875,-0.185 22.875,-1.27 22.595,-1.55 21.505,-1.55 20.525,-0.57 20.525,0.09 20.675,0.24 20.884,0.24 21.524,-0.4 v2(21.65,-0.4)
FT_D19: IC5.E10 IC6.63 | length 14.4
  Top w0.2: v1@18.875,-1.6 IC6.63@19.525,-1.6
  Top w0.4: v2(24.85,2.8) IC5.E10@25.25,2.4
  L6 w0.1: v1(18.85,-1.6) 19.21,-1.6 19.403,-1.407 19.403,-0.55 19.4,-0.547 19.4,1.99 19.8,2.39 20.35,2.39 20.525,2.565 20.525,3.172 20.718,3.365 20.875,3.365 20.975,3.265 20.975,2.365 21.14,2.2 21.355,2.2 21.5,2.345 21.5,2.89 21.625,3.015 21.95,3.015 22.1,2.865 22.1,2.59 22.25,2.44 23.5,2.44 23.675,2.615 23.675,3.015 23.9,3.24 24.41,3.24 v2(24.85,2.8)
FT_D20: IC5.A5 IC6.64 | length 14.4
  Top w0.2: IC6.64@19.525,-1.2 v1(20.175,-1.2)
  Top w0.4: v2(21.65,-1.2) IC5.A5@22.05,-1.6
  L5 w0.1: v1(20.175,-1.2) 19.965,-1.41 19.525,-1.41 19.2,-1.085 19.2,0.24 19.35,0.39 19.65,0.39 19.8,0.54 19.8,1.015 19.665,1.15 18.215,1.15 17.975,1.39 17.975,1.84 18.175,2.04 19.625,2.04 20.025,1.64 20.975,1.64 21.15,1.465 21.15,0.257 21.357,0.05 21.865,0.05 22.1,-0.185 22.1,-0.75 v2(21.65,-1.2)
FT_D21: IC5.F9 IC6.65 | length 14.8
  Top w0.2: v1@18.875,-0.8 IC6.65@19.525,-0.8
  Top w0.4: v2(25.65,2) IC5.F9@26.05,1.6
  L6 w0.1: v1(18.85,-0.8) 19.06,-0.8 19.2,-0.66 19.2,2.515 19.925,3.24 20.31,3.24 20.685,3.615 21.14,3.615 21.54,3.215 23.45,3.215 23.7,3.465 23.7,3.79 23.9,3.99 25.8,3.99 26.025,3.765 26.025,2.275 25.75,2 v2(25.65,2)
FT_D22: IC5.E8 IC6.66 | length 17.2
  Top w0.2: IC6.66@19.525,-0.4 v1(20.175,-0.4)
  Top w0.4: v2(24.85,1.2) IC5.E8@25.25,0.8
  L5 w0.1: v1(20.175,-0.4) 20.175,-0.503 20.525,-0.853 20.525,-1.345 20.22,-1.65 19.44,-1.65 18.94,-1.15 18.705,-1.15 18.5,-0.945 18.5,-0.535 18.5,0.565 17.775,1.29 17.775,2.09 18.45,2.765 19.025,2.765 19.44,2.35 20.69,2.35 21.39,1.65 23.51,1.65 23.7,1.84 23.7,2.175 23.875,2.35 24.195,2.35 24.4,2.145 24.4,1.65 v2(24.85,1.2)
FT_D23: IC5.A8 IC6.67 | length 14.6
  Top w0.2: v1@18.875,0 IC6.67@19.525,0
  Top w0.4: v2(21.65,1.2) IC5.A8@22.05,0.8
  L4 w0.1: v1(18.85,0) 18.5,0.35 18.5,2.865 18.375,2.99 17.825,2.99 17.625,2.79 17.625,-0.985 17.89,-1.25 19.135,-1.25 19.325,-1.06 19.325,-0.26 19.585,0 20.402,0 21.602,1.2 v2(21.65,1.2)
FT_D24: IC5.K11 IC6.69 | length 14.9
  Top w0.2: v1@18.875,0.8 IC6.69@19.525,0.8
  Top w0.4: v2(28.85,3.6) IC5.K11@29.25,3.2
  L4 w0.1: v1(18.85,0.8) 18.85,0.59 19.1,0.34 19.62,0.34 20.08,0.8 20.919,0.8 21.3,1.181 21.3,1.345 21.595,1.64 25.825,1.64 26,1.465 26,0.915 26.165,0.75 26.66,0.75 26.9,0.99 26.9,2.215 27.1,2.415 27.36,2.415 27.6,2.655 27.6,2.845 27.905,3.15 28.4,3.15 v2(28.85,3.6)
FT_D25: IC5.K12 IC6.70 | length 15.1
  Top w0.2: IC6.70@19.525,1.2 v1(20.175,1.2)
  Top w0.4: v2(28.85,4.4) IC5.K12@29.25,4
  L4 w0.1: v1(20.175,1.2) 20.375,1 20.836,1 21.1,1.264 21.1,1.465 20.95,1.615 20.95,1.975 21.5,2.525 21.5,3.015 21.7,3.215 21.975,3.215 22.1,3.09 22.1,2.575 22.31,2.365 22.625,2.365 22.8,2.54 22.8,3.04 22.975,3.215 23.425,3.215 23.625,3.015 23.625,2.59 23.825,2.39 26.65,2.39 26.8,2.54 26.8,2.845 27.105,3.15 27.485,3.15 27.6,3.265 27.6,3.645 27.905,3.95 28.685,3.95 28.85,4.115 v2(28.85,4.4)
FT_D26: IC5.J12 IC6.71 | length 15.8
  Top w0.2: v1@18.875,1.6 IC6.71@19.525,1.6
  Top w0.4: v2(28.05,4.4) IC5.J12@28.45,4
  L4 w0.1: v1(18.85,1.6) 19.2,1.25 19.2,0.79 19.375,0.615 19.575,0.615 19.825,0.865 19.825,1.345 20.08,1.6 20.585,1.6 20.75,1.765 20.75,2.08 21.3,2.63 21.3,3.79 21.5,3.99 21.85,3.99 22.05,3.79 22.05,3.45 22.25,3.25 22.66,3.25 22.875,3.465 22.875,3.815 23.075,4.015 23.475,4.015 23.625,3.865 23.625,3.45 23.825,3.25 26.595,3.25 26.8,3.455 26.8,3.69 27.16,4.05 27.7,4.05 v2(28.05,4.4)
FT_D27: IC5.G12 IC6.72 | length 16.8
  Top w0.2: IC6.72@19.525,2 v1(20.175,2)
  Top w0.4: v2(26.45,4.4) IC5.G12@26.85,4
  L4 w0.1: v1(20.175,2) 20.387,2 21.1,2.713 21.1,4.115 21.275,4.29 21.275,5.326 21.564,5.615 21.875,5.615 22.025,5.465 22.025,4.215 22.25,3.99 22.7,3.99 22.85,4.14 22.85,5.465 23,5.615 23.45,5.615 23.625,5.44 23.625,4.215 23.825,4.015 24.325,4.015 24.45,4.14 24.45,5.465 24.6,5.615 25.075,5.615 25.25,5.44 25.25,5.04 25.44,4.85 25.957,4.85 26.407,4.4 v2(26.45,4.4)
FT_D28: IC5.L13 IC6.73 | length 17.1
  Top w0.2: v1@18.875,2.4 IC6.73@19.525,2.4
  Top w0.4: v2(29.65,5.2) IC5.L13@30.05,4.8
  L4 w0.1: v1(18.85,2.4) 18.85,2.705 19.2,3.055 19.2,3.267 19.411,3.479 19.636,3.479 19.825,3.29 19.825,2.655 20.065,2.415 20.308,2.415 20.85,2.957 20.85,4.148 21.05,4.348 21.05,5.384 21.481,5.815 25.65,5.815 26.1,5.365 26.1,4.99 26.275,4.815 29.265,4.815 v2(29.65,5.2)
FT_D29: IC5.G13 IC6.74 | length 15
  Top w0.2: IC6.74@19.525,2.8 v1(20.175,2.8)
  Top w0.4: v2(26.45,5.2) IC5.G13@26.85,4.8
  L4 w0.1: v1(20.175,2.8) 20.41,2.8 20.65,3.04 20.65,3.62 20.25,4.02 20.25,4.64 20.1,4.79 19.625,4.79 19.475,4.64 19.475,4.15 19.215,3.89 18.95,3.89 18.775,4.065 18.775,4.507 19.433,5.165 20.549,5.165 21.399,6.015 25.85,6.015 26.45,5.415 v2(26.45,5.2)
FT_D30: IC5.J13 IC6.75 | length 15.3
  Top w0.2: v1@18.875,3.2 IC6.75@19.525,3.2
  Top w0.4: v2(28.05,5.2) IC5.J13@28.45,4.8
  L4 w0.1: v1(18.85,3.2) 18.365,3.2 17.825,3.74 17.825,4.09 18.225,4.49 18.225,5.39 18.4,5.565 20.383,5.565 21.233,6.415 27.272,6.415 28.05,5.637 v2(28.05,5.2)
FT_D31: IC5.H13 IC6.76 | length 15.1
  Top w0.2: IC6.76@19.525,3.6 v1(20.175,3.6)
  Top w0.4: v2(27.25,5.2) IC5.H13@27.65,4.8
  L4 w0.1: v1(20.175,3.6) 20.175,3.812 19.972,4.015 19.625,4.015 19.175,3.565 18.775,3.565 18.575,3.765 18.575,4.59 19.35,5.365 20.466,5.365 21.316,6.215 27.189,6.215 27.773,5.632 27.773,5.438 27.535,5.2 v2(27.25,5.2)
FT_OEN: IC5.F12 IC6.13 | length 16
  Top w0.2: IC6.13@13.825,4.5 v1(13.825,5.15)
  Top w0.4: v2(25.65,4.4) IC5.F12@26.05,4
  L6 w0.1: v1(13.825,5.15) 15.665,6.99 23.139,6.99 23.214,6.915 23.431,6.915 24.581,5.765 25.083,5.765 25.28,5.568 25.822,5.568 26,5.39 26,4.75 v2(25.65,4.4)
FT_RDN: IC5.D12 IC6.12 | length 15
  Top w0.2: v1(14.225,3.85) IC6.12@14.225,4.5
  Top w0.4: v2(24.05,4.4) IC5.D12@24.45,4
  L6 w0.1: v1(14.225,3.85) 15.025,4.65 15.025,5.765 15.275,6.015 20.26,6.015 20.76,6.515 23.266,6.515 24.5,5.281 24.5,4.565 24.335,4.4 v2(24.05,4.4)
FT_RESETN: C127.1 IC5.L12 IC6.15 R55.1 | length 35.2
  Top w0.2: IC6.15@13.025,4.5 v1(13.025,5.15)
  Top w0.4: v2(29.65,4.4) IC5.L12@30.05,4
  L4 w0.1: v1(5.45,8.665) 5.45,9.29 7.86,11.7 8.38,11.7 9.225,10.855 9.225,9.39 10.9,7.715 10.9,6.765 12.1,5.565 12.61,5.565 v1(13.025,5.15)
  L6 w0.1: v1(13.025,5.15) 15.265,7.39 23.305,7.39 23.38,7.315 23.597,7.315 24.747,6.165 25.249,6.165 25.446,5.968 25.988,5.968 26.191,5.765 27.225,5.765 27.65,5.34 27.65,5.04 27.85,4.84 29.2,4.84 29.64,4.4 v2(29.65,4.4)
  Bottom w0.4: C127.1@4.875,7.59 C127.1@4.875,7.64 R55.1@4.875,8.69 5.425,8.69 v1(5.45,8.665)
FT_RXFN: IC5.C11 IC6.9 | length 12.5
  Top w0.2: IC6.9@15.425,4.5 v1(15.425,5.15)
  Top w0.4: v2(23.25,3.6) IC5.C11@23.65,3.2
  L6 w0.1: v1(15.425,5.15) 15.447,5.15 16.112,5.815 20.375,5.815 20.875,6.315 23.183,6.315 23.65,5.848 23.65,4.023 23.25,3.623 v2(23.25,3.6)
FT_SIWUN: IC6.10 R53.1 | length 1.3
  Top w0.2: v1(15.025,3.85) IC6.10@15.025,4.5
  Bottom w0.3: R53.1@14.975,4.49 15.025,4.44 v1(15.025,3.85)
FT_TXEN: IC5.C13 IC6.8 | length 14.8
  Top w0.2: v1(15.825,3.85) IC6.8@15.825,4.5
  Top w0.4: v2(23.25,5.2) IC5.C13@23.65,4.8
  L6 w0.1: v1@15.8,3.875 15.8,3.85 15.8,3.09 15.55,2.84 14.95,2.84 14.625,3.165 14.625,3.967 15.38,4.723 15.633,4.723 15.8,4.89 15.8,5.22 16.195,5.615 20.5,5.615 21,6.115 23.1,6.115 23.25,5.965 v2(23.25,5.2)
FT_VBUS: IC6.37 R50.1 R51.2 | length 3.1
  Top w0.2: v1(8.775,-3.81) 9.385,-3.2 IC6.37@10.525,-3.2
  Bottom w0.6: R50.1@8.775,-4.36 R51.2@8.775,-3.26
FT_WAKEUPN: IC5.H10 IC6.16 R54.1 | length 21.6
  Top w0.2: v1(12.625,3.85) IC6.16@12.625,4.5
  Top w0.4: v2(27.25,2.8) IC5.H10@27.65,2.4
  L6 w0.1: v1(12.625,3.85) 13.4,4.625 13.4,5.24 15.35,7.19 23.222,7.19 23.297,7.115 23.514,7.115 24.664,5.965 25.166,5.965 25.363,5.768 25.905,5.768 26.108,5.565 26.58,5.565 26.8,5.345 26.8,3.25 v2(27.25,2.8)
  Bottom w0.3: R54.1@11.95,4.49 11.95,4.361 12.461,3.85 v1(12.625,3.85)
FT_WRN: IC5.E12 IC6.11 | length 14.5
  Top w0.2: IC6.11@14.625,4.5 v1(14.625,5.15)
  Top w0.4: v2(24.85,4.4) IC5.E12@25.25,4
  L6 w0.1: v1(14.625,5.15) 14.625,5.667 15.748,6.79 23.057,6.79 23.132,6.715 23.349,6.715 24.499,5.565 25,5.565 25.2,5.365 25.2,4.75 v2(24.85,4.4)
FT_XTAL_N: C126.1 IC6.22 XT1.1 | length 8.8
  Top w0.2: IC6.22@10.525,2.8 11.175,2.8 v1(11.275,2.7)
  Top w0.4: C126.1@8.025,6.265 v1(8.775,6.265)
  L6 w0.1: v1(8.775,6.265) cw(c8.715,6.205) 8.8,6.205 8.8,5.965 cw(c8.517,5.965) 8.717,5.765 8.534,5.581 ccw(c9.52,4.595) 8.125,4.595 8.125,4.075 ccw(c9.3,4.075) 9.3,2.9 10.9,2.9 cw(c10.9,2.477) 11.199,2.776 v1(11.275,2.7)
  Bottom w0.4: XT1.1@7.925,6.615 8.275,6.265 v1(8.775,6.265)
FT_XTAL_P: C124.1 IC6.21 XT1.3 | length 7.3
  Top w0.2: IC6.21@10.525,3.2 11.175,3.2 v1(11.275,3.3)
  Top w0.4: C124.1@8.525,5.265 v1(9.275,5.265)
  L6 w0.1: v1@9.275,5.344 9.194,5.425 ccw(c8.916,5.147) 8.916,5.54 ccw(c8.916,5.199) 8.675,5.44 ccw(c9.52,4.595) 8.325,4.595 8.325,4.075 ccw(c9.3,4.075) 9.3,3.1 10.9,3.1 ccw(c10.9,3.523) 11.199,3.224 v1(11.275,3.3)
